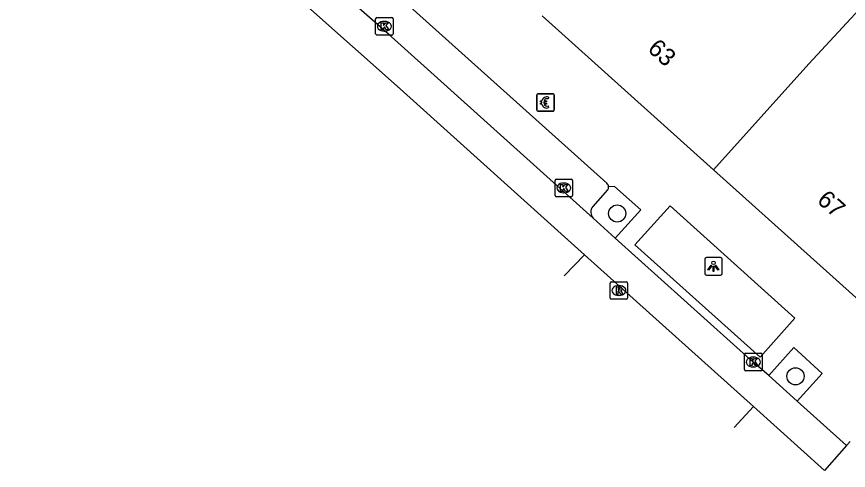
# Model space of a CAD drawing. Extents: x 161771 to 163125, y 382479 to 383177.
# Drawn here: x 162018.89 to 162066.34, y 382721.36 to 382747.23 of the extents above; entities that cross this region are included whole.
import ezdxf

# ---------------------------------------------------------------- set-up
doc = ezdxf.new("R2010")
doc.units = 0
for name, color, linetype in [('IMGEO_Betaalautomaat', 7, 'Continuous'), ('IMGEO_Boom', 7, 'Continuous'), ('IMGEO_Kolk', 7, 'Continuous'), ('IMGEO_Lichtpunt', 7, 'Continuous'), ('IMGEO_Pand', 7, 'Continuous'), ('IMGEO_Pand_nummerreeks', 7, 'Continuous'), ('IMGEO_Parkeervlak_open', 7, 'Continuous'), ('IMGEO_Rijbaan_lokaal_gesloten', 7, 'Continuous'), ('IMGEO_Rijbaan_lokaal_open', 7, 'Continuous'), ('IMGEO_Rioolput', 7, 'Continuous'), ('IMGEO_Voetpad_open', 7, 'Continuous')]:
    doc.layers.add(name, color=color, linetype=linetype)

msp = doc.modelspace()

# ---------------------------------------------------------------- linework, layer by layer
at = {"layer": 'IMGEO_Betaalautomaat'}
for p, q in [((162048.568, 382741.911), (162048.568, 382742.752)), ((162048.568, 382742.752), (162048.568, 382741.911)), ((162048.643, 382742.835), (162049.484, 382742.835)), ((162049.484, 382742.835), (162048.643, 382742.835)), ((162049.23, 382742.64), (162049.213, 382742.54)), ((162049.567, 382742.761), (162049.567, 382741.92)), ((162049.567, 382741.92), (162049.567, 382742.761)), ((162048.851, 382742.299), (162048.851, 382742.367)), ((162048.972, 382742.367), (162048.972, 382742.299)), ((162049.493, 382741.836), (162048.652, 382741.836)), ((162048.652, 382741.836), (162049.493, 382741.836)), ((162049.217, 382742.134), (162049.239, 382742.047))]:
    msp.add_line(p, q, dxfattribs=at)
for points in [[(162048.851, 382742.367), (162048.782, 382742.367), (162048.782, 382742.436), (162048.861, 382742.436)], [(162048.856, 382742.23), (162048.782, 382742.23), (162048.782, 382742.299), (162048.851, 382742.299)], [(162048.983, 382742.436), (162049.13, 382742.436), (162049.13, 382742.367), (162048.972, 382742.367)], [(162048.972, 382742.299), (162049.13, 382742.299), (162049.13, 382742.23), (162048.986, 382742.23)]]:
    msp.add_lwpolyline(points, dxfattribs=at)
for centre, radius, start, end in [((162048.646, 382742.758), 0.0779, 92.4484, 184.2845), ((162048.646, 382742.758), 0.0779, 92.4484, 184.2845), ((162049.144, 382742.36), 0.293, 73.014, 165.0139), ((162049.49, 382742.758), 0.0779, 2.4484, 94.2845), ((162049.49, 382742.758), 0.0779, 2.4484, 94.2845), ((162049.117, 382742.285), 0.267, 191.8096, 297.0389), ((162049.15, 382742.373), 0.179, 69.3236, 159.5683), ((162049.15, 382742.3), 0.179, 202.7625, 291.8693), ((162048.646, 382741.914), 0.0779, 182.4484, 274.2845), ((162048.646, 382741.914), 0.0779, 182.4484, 274.2845), ((162049.49, 382741.914), 0.0779, 272.4484, 4.2845), ((162049.49, 382741.914), 0.0779, 272.4484, 4.2845)]:
    msp.add_arc(centre, radius, start, end, dxfattribs=at)
at = {"layer": 'IMGEO_Boom'}
for centre in [(162053.156, 382736.006), (162063.329, 382726.721)]:
    msp.add_circle(centre, 0.489, dxfattribs=at)
at = {"layer": 'IMGEO_Kolk'}
for p, q in [((162039.373, 382746.255), (162039.373, 382747.107)), ((162039.448, 382747.181), (162040.3, 382747.181)), ((162039.861, 382746.961), (162039.886, 382746.961)), ((162040.374, 382747.107), (162040.374, 382746.255)), ((162040.3, 382746.181), (162039.448, 382746.181)), ((162039.884, 382746.401), (162039.859, 382746.401)), ((162049.609, 382737.037), (162049.609, 382737.889)), ((162049.684, 382737.963), (162050.536, 382737.963)), ((162050.61, 382737.889), (162050.61, 382737.037)), ((162050.097, 382737.743), (162050.122, 382737.743)), ((162050.536, 382736.963), (162049.684, 382736.963)), ((162050.12, 382737.183), (162050.095, 382737.183)), ((162060.42, 382727.107), (162060.42, 382727.959)), ((162060.495, 382728.033), (162061.347, 382728.033)), ((162061.421, 382727.959), (162061.421, 382727.107)), ((162060.908, 382727.813), (162060.933, 382727.813)), ((162061.347, 382727.033), (162060.495, 382727.033)), ((162060.931, 382727.253), (162060.906, 382727.253))]:
    msp.add_line(p, q, dxfattribs=at)
for points in [[(162039.373, 382746.255), (162039.373, 382747.107)], [(162039.448, 382747.181), (162040.3, 382747.181)], [(162040.374, 382747.107), (162040.374, 382746.255)], [(162039.694, 382746.881), (162039.817, 382746.881), (162039.817, 382746.73), (162039.947, 382746.881), (162040.111, 382746.881), (162039.965, 382746.73), (162040.118, 382746.481), (162039.966, 382746.481), (162039.881, 382746.645), (162039.817, 382746.578), (162039.817, 382746.481), (162039.694, 382746.481), (162039.694, 382746.881)], [(162040.3, 382746.181), (162039.448, 382746.181)], [(162049.609, 382737.037), (162049.609, 382737.889)], [(162049.684, 382737.963), (162050.536, 382737.963)], [(162050.61, 382737.889), (162050.61, 382737.037)], [(162049.93, 382737.663), (162050.053, 382737.663), (162050.053, 382737.512), (162050.183, 382737.663), (162050.347, 382737.663), (162050.201, 382737.512), (162050.354, 382737.263), (162050.202, 382737.263), (162050.117, 382737.427), (162050.053, 382737.36), (162050.053, 382737.263), (162049.93, 382737.263), (162049.93, 382737.663)], [(162050.536, 382736.963), (162049.684, 382736.963)], [(162060.42, 382727.107), (162060.42, 382727.959)], [(162060.495, 382728.033), (162061.347, 382728.033)], [(162061.421, 382727.959), (162061.421, 382727.107)], [(162060.741, 382727.733), (162060.864, 382727.733), (162060.864, 382727.582), (162060.994, 382727.733), (162061.158, 382727.733), (162061.012, 382727.582), (162061.165, 382727.333), (162061.013, 382727.333), (162060.928, 382727.497), (162060.864, 382727.43), (162060.864, 382727.333), (162060.741, 382727.333), (162060.741, 382727.733)], [(162061.347, 382727.033), (162060.495, 382727.033)]]:
    msp.add_lwpolyline(points, dxfattribs=at)
for centre, start, end in [((162039.45, 382747.105), 91.552, 178.448), ((162039.45, 382747.105), 91.552, 178.448), ((162040.298, 382747.105), 1.552, 88.448), ((162040.298, 382747.105), 1.552, 88.448), ((162039.45, 382746.257), 181.552, 268.448), ((162039.45, 382746.257), 181.552, 268.448), ((162040.298, 382746.257), 271.552, 358.448), ((162040.298, 382746.257), 271.552, 358.448), ((162049.686, 382737.887), 91.552, 178.448), ((162049.686, 382737.887), 91.552, 178.448), ((162050.534, 382737.887), 1.552, 88.448), ((162050.534, 382737.887), 1.552, 88.448), ((162049.686, 382737.039), 181.552, 268.448), ((162049.686, 382737.039), 181.552, 268.448), ((162050.534, 382737.039), 271.552, 358.448), ((162050.534, 382737.039), 271.552, 358.448), ((162060.497, 382727.957), 91.552, 178.448), ((162060.497, 382727.957), 91.552, 178.448), ((162061.345, 382727.957), 1.552, 88.448), ((162061.345, 382727.957), 1.552, 88.448), ((162060.497, 382727.109), 181.552, 268.448), ((162060.497, 382727.109), 181.552, 268.448), ((162061.345, 382727.109), 271.552, 358.448), ((162061.345, 382727.109), 271.552, 358.448)]:
    msp.add_arc(centre, 0.0765, start, end, dxfattribs=at)
for centre, major_axis, ratio, start_param, end_param in [((162039.86, 382746.681), (-0.387, 0.002), 0.722429, 4.712389, 7.853982), ((162039.885, 382746.681), (-0.39, 0.002), 0.717154, 1.570796, 4.712389), ((162050.096, 382737.463), (-0.387, 0.002), 0.722429, 4.712389, 7.853982), ((162050.121, 382737.463), (-0.39, 0.002), 0.717154, 1.570796, 4.712389), ((162060.907, 382727.533), (-0.387, 0.002), 0.722429, 4.712389, 7.853982), ((162060.932, 382727.533), (-0.39, 0.002), 0.717154, 1.570796, 4.712389)]:
    msp.add_ellipse(centre, major_axis=major_axis, ratio=ratio, start_param=start_param, end_param=end_param, dxfattribs=at)
at = {"layer": 'IMGEO_Lichtpunt'}
for p, q in [((162058.148, 382733.393), (162058.148, 382732.586)), ((162058.148, 382733.393), (162058.148, 382732.586)), ((162059.05, 382733.488), (162058.242, 382733.488)), ((162059.05, 382733.488), (162058.242, 382733.488)), ((162059.144, 382732.586), (162059.144, 382733.393)), ((162059.144, 382732.586), (162059.144, 382733.393)), ((162058.242, 382732.492), (162059.05, 382732.492)), ((162058.242, 382732.492), (162059.05, 382732.492))]:
    msp.add_line(p, q, dxfattribs=at)
for points in [[(162058.522, 382733.057), (162058.561, 382733.029), (162058.373, 382732.767), (162058.335, 382732.794), (162058.522, 382733.057)], [(162058.624, 382733.009), (162058.671, 382733.009), (162058.671, 382732.687), (162058.624, 382732.687), (162058.624, 382733.009)], [(162058.734, 382733.029), (162058.772, 382733.056), (162058.959, 382732.794), (162058.92, 382732.766), (162058.734, 382733.029)]]:
    msp.add_lwpolyline(points, dxfattribs=at)
msp.add_circle((162058.647, 382733.191), 0.0994, dxfattribs=at)
for centre, start, end in [((162058.242, 382733.393), 90, 180), ((162058.242, 382733.393), 90, 180), ((162059.05, 382733.393), 0, 90), ((162059.05, 382733.393), 0, 90), ((162058.242, 382732.586), 180, 270), ((162058.242, 382732.586), 180, 270), ((162059.05, 382732.586), 270, 0), ((162059.05, 382732.586), 270, 360)]:
    msp.add_arc(centre, 0.0946, start, end, dxfattribs=at)
at = {"layer": 'IMGEO_Pand'}
for points in [[(162058.659, 382738.492), (162064.092, 382744.546), (162069.12, 382750), (162093.305, 382776.234)], [(162048.871, 382747.277), (162058.659, 382738.492)], [(162058.659, 382738.492), (162068.232, 382729.901)]]:
    msp.add_lwpolyline(points, dxfattribs=at)
at = {"layer": 'IMGEO_Parkeervlak_open'}
msp.add_lwpolyline([(162052.609, 382737.347), (162051.767, 382736.41)], dxfattribs=at)
for centre, radius, start, end in [((162052.393, 382737.512), 0.272, 322.5213, 1.6052), ((162052.154, 382736.088), 0.503, 140.2884, 224.143)]:
    msp.add_arc(centre, radius, start, end, dxfattribs=at)
at = {"layer": 'IMGEO_Rijbaan_lokaal_gesloten'}
for points in [[(162051.295, 382733.653), (162040.771, 382743.106), (162021.402, 382760.333), (162018.892, 382762.567)], [(162051.793, 382735.738), (162040.256, 382746.1), (162037.949, 382748.131)], [(162051.793, 382735.738), (162053.042, 382734.604)], [(162061.805, 382726.762), (162060.921, 382727.533), (162053.042, 382734.604)], [(162060.923, 382725.005), (162051.295, 382733.653)], [(162061.805, 382726.762), (162063.425, 382725.308)], [(162066.242, 382722.779), (162063.425, 382725.308)], [(162066.242, 382722.779), (162064.984, 382721.357), (162060.923, 382725.005)]]:
    msp.add_lwpolyline(points, dxfattribs=at)
at = {"layer": 'IMGEO_Rijbaan_lokaal_open'}
for points in [[(162051.295, 382733.653), (162050.126, 382732.448)], [(162059.829, 382723.81), (162060.923, 382725.005)], [(162066.446, 382723.002), (162066.242, 382722.779)]]:
    msp.add_lwpolyline(points, dxfattribs=at)
at = {"layer": 'IMGEO_Rioolput'}
for p, q in [((162052.751, 382731.184), (162052.751, 382732.036)), ((162052.826, 382732.11), (162053.678, 382732.11)), ((162053.239, 382731.89), (162053.264, 382731.89)), ((162053.752, 382732.036), (162053.752, 382731.184)), ((162053.262, 382731.33), (162053.237, 382731.33)), ((162053.678, 382731.11), (162052.826, 382731.11))]:
    msp.add_line(p, q, dxfattribs=at)
for points in [[(162052.751, 382731.184), (162052.751, 382732.036)], [(162052.826, 382732.11), (162053.678, 382732.11)], [(162053.34, 382731.808), (162053.088, 382731.81), (162053.088, 382731.41)], [(162053.266, 382731.729), (162053.212, 382731.729), (162053.212, 382731.648)], [(162053.752, 382732.036), (162053.752, 382731.184)], [(162053.088, 382731.41), (162053.212, 382731.41), (162053.212, 382731.572), (162053.223, 382731.572)], [(162053.212, 382731.648), (162053.264, 382731.648)], [(162053.27, 382731.543), (162053.341, 382731.41), (162053.481, 382731.41), (162053.416, 382731.536)], [(162053.678, 382731.11), (162052.826, 382731.11)]]:
    msp.add_lwpolyline(points, dxfattribs=at)
for centre, radius, start, end in [((162052.828, 382732.034), 0.0765, 91.552, 178.448), ((162052.828, 382732.034), 0.0765, 91.552, 178.448), ((162053.272, 382731.633), 0.0964, 77.0061, 93.1865), ((162053.286, 382731.69), 0.0378, 276.6634, 79.6772), ((162053.339, 382731.698), 0.109, 350.3612, 89.416), ((162053.676, 382732.034), 0.0765, 1.552, 88.448), ((162053.676, 382732.034), 0.0765, 1.552, 88.448), ((162053.222, 382731.519), 0.0533, 26.0293, 88.6989), ((162053.248, 382731.837), 0.19, 274.7715, 282.9687), ((162053.337, 382731.698), 0.112, 277.5842, 350.9817), ((162053.321, 382731.483), 0.108, 29.5134, 73.7905), ((162052.828, 382731.186), 0.0765, 181.552, 268.448), ((162052.828, 382731.186), 0.0765, 181.552, 268.448), ((162053.676, 382731.186), 0.0765, 271.552, 358.448), ((162053.676, 382731.186), 0.0765, 271.552, 358.448)]:
    msp.add_arc(centre, radius, start, end, dxfattribs=at)
for centre, major_axis, ratio, start_param, end_param in [((162053.238, 382731.61), (-0.387, 0.002), 0.722429, 4.712389, 7.853982), ((162053.263, 382731.61), (-0.39, 0.002), 0.717154, 1.570796, 4.712389)]:
    msp.add_ellipse(centre, major_axis=major_axis, ratio=ratio, start_param=start_param, end_param=end_param, dxfattribs=at)
at = {"layer": 'IMGEO_Voetpad_open'}
for points in [[(162052.558, 382737.727), (162043.559, 382745.806), (162039.858, 382749.129)], [(162053.042, 382734.604), (162054.497, 382736.22), (162053.01, 382737.548), (162052.665, 382737.52)], [(162061.305, 382727.819), (162063.29, 382730.033), (162056.171, 382736.437), (162054.17, 382734.22), (162061.305, 382727.819)], [(162063.425, 382725.308), (162064.843, 382726.887), (162063.239, 382728.372), (162061.805, 382726.762)]]:
    msp.add_lwpolyline(points, dxfattribs=at)
msp.add_arc((162052.397, 382737.513), 0.268, 1.5986, 53.071, dxfattribs=at)

# ---------------------------------------------------------------- texts
at = {"layer": 'IMGEO_Pand_nummerreeks'}
for s, rotation, p in [('63', 318.0911, (162054.833, 382745.312)), ('67', 318.0809, (162064.496, 382736.681))]:
    msp.add_text(s, height=1, rotation=rotation, dxfattribs=at).set_placement(p)

doc.saveas('drawing.dxf')
